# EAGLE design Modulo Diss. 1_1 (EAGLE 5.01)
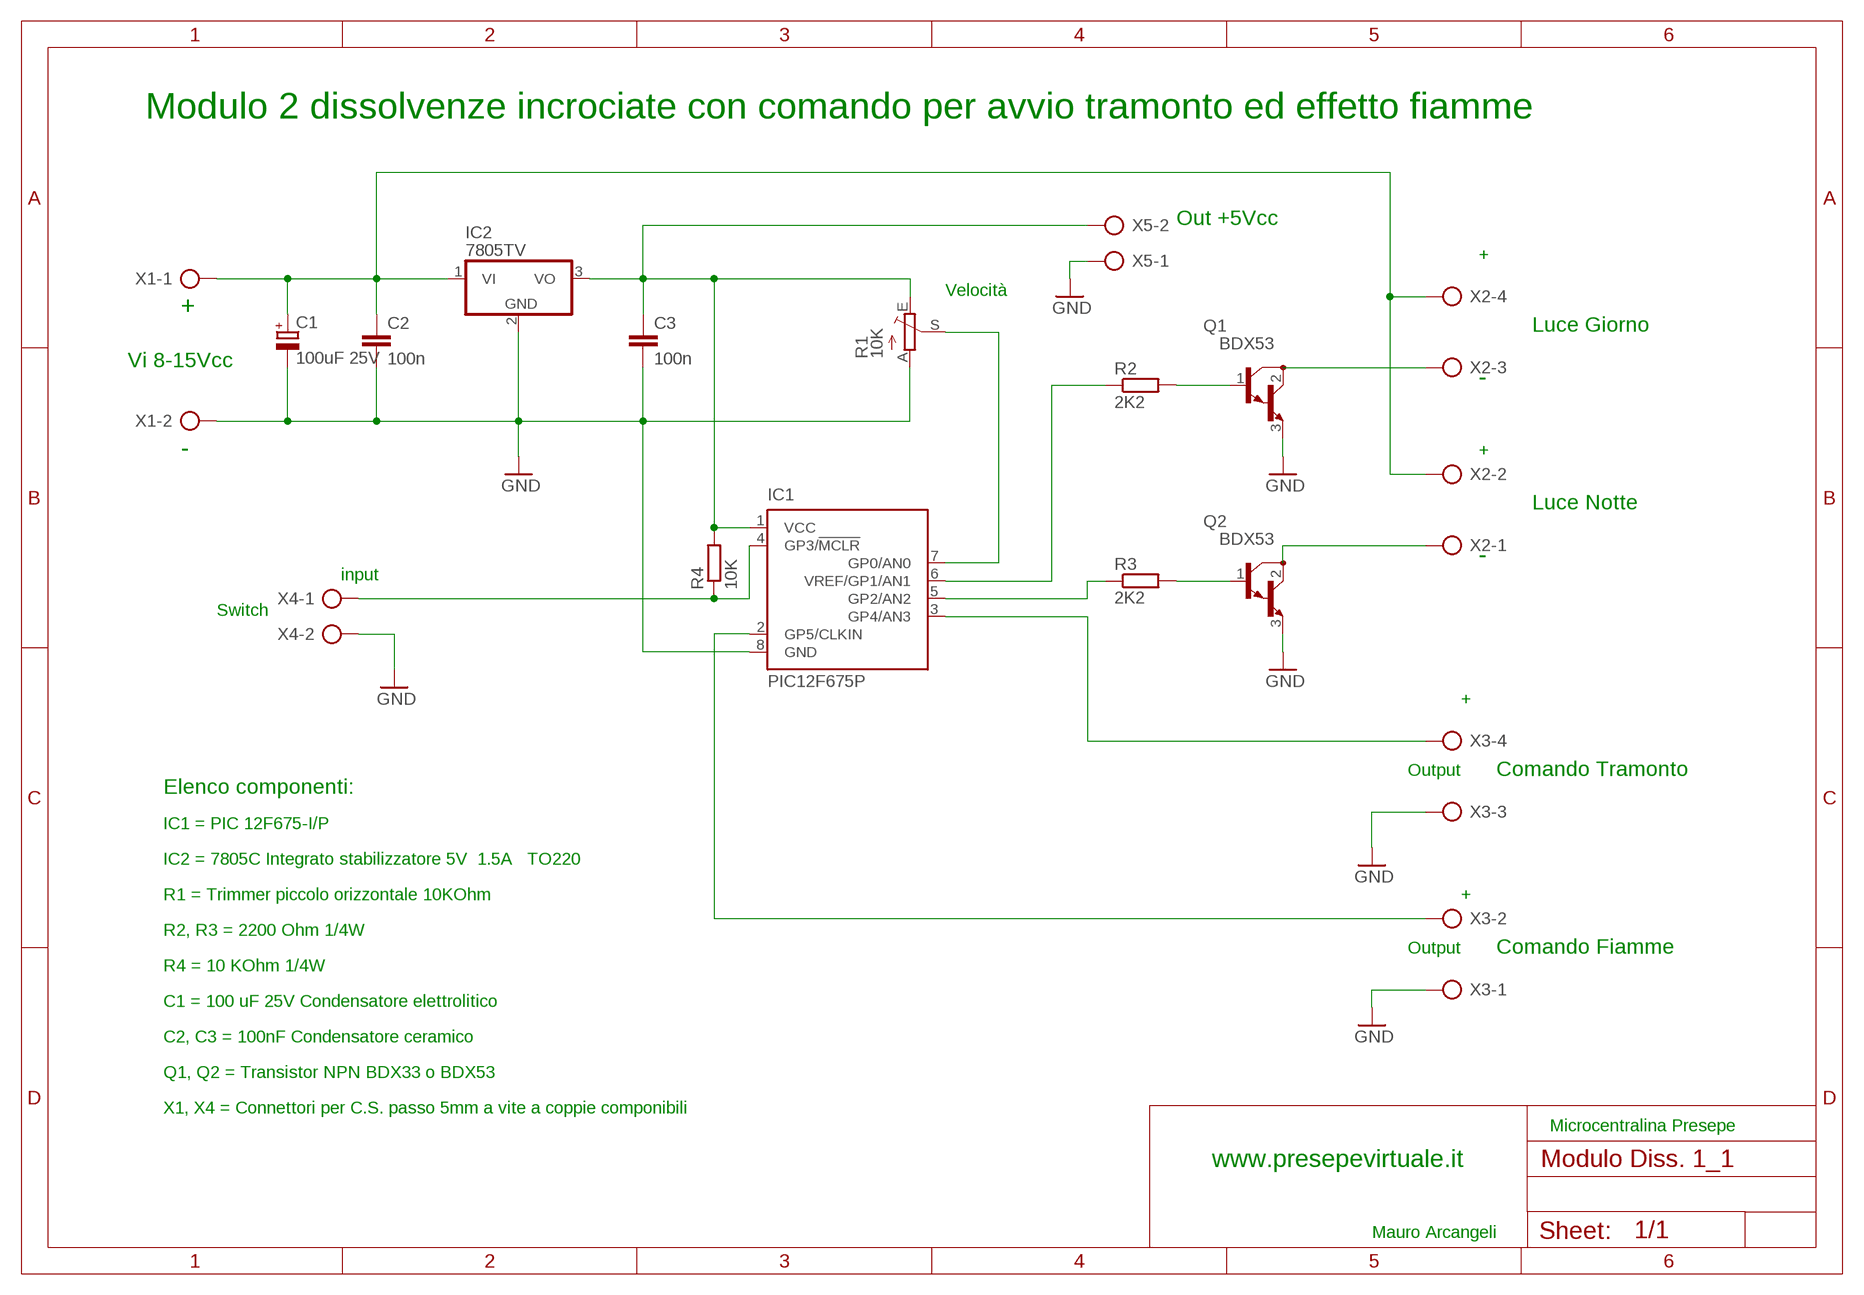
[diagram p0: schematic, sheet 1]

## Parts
C1  100uF 25V  CPOL-EUE3.5-8  [E3,5-8]
C2  100n  C-EU050-025X075  [C050-025X075]
C3  100n  C-EU050-025X075  [C050-025X075]
IC1  PIC12F675P  [DIL8]
IC2  7805TV  [TO220V]
Q1  BDX53  [TO220]
Q2  BDX53  [TO220]
R1  10K  TRIM_EU-PT10  [PT-10]
R2  2K2  R-EU_0207/12  [0207/12]
R3  2K2  R-EU_0207/12  [0207/12]
R4  10K  R-EU_0207/12  [0207/12]
X1  AK500/2  [AK500/2]
X2  AK500/4  [AK500/4]
X3  AK500/4  [AK500/4]
X4  AK500/2  [AK500/2]
X5  AK500/2  [AK500/2]

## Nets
GND: C1.- C2.2 C3.2 IC1.8(GND) IC2.2(GND) Q1.3(E) Q2.3(E) R1.A X1.2 X3.1 X3.3 X4.2 X5.1
N$1: C1.+ C2.1 IC2.1(VI) X1.1 X2.2 X2.4
N$2: C3.1 IC1.1(VCC) IC2.3(VO) R1.E R4.2 X5.2
N$4: Q1.1(B) R2.2
N$5: Q2.1(B) R3.2
N$6: Q2.2(C) X2.1
N$7: Q1.2(C) X2.3
N$8: IC1.7(GP0/AN0) R1.S
N$9: IC1.4(GP3/!MCLR) R4.1 X4.1
N$10: IC1.6(VREF/GP1/AN1) R2.1
N$11: IC1.5(GP2/AN2) R3.1
N$12: IC1.3(GP4/AN3) X3.4
N$13: IC1.2(GP5/CLKIN) X3.2

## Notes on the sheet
- Modulo 2 dissolvenze incrociate con comando per avvio tramonto ed effetto fiamme
- Out +5Vcc
- +
- Velocità
- +
- Luce Giorno
- Vi 8-15Vcc
- -
- - | +
- Luce Notte
- -
- input
- Switch
- +
- Output | Comando Tramonto
- Elenco componenti:
- IC1 = PIC 12F675-I/P
- IC2 = 7805C Integrato stabilizzatore 5V  1.5A   TO220
- R1 = Trimmer piccolo orizzontale 10KOhm | +
- R2, R3 = 2200 Ohm 1/4W
- Output | Comando Fiamme
- R4 = 10 KOhm 1/4W
- C1 = 100 uF 25V Condensatore elettrolitico
- C2, C3 = 100nF Condensatore ceramico
- Q1, Q2 = Transistor NPN BDX33 o BDX53
- X1, X4 = Connettori per C.S. passo 5mm a vite a coppie componibili
- Microcentralina Presepe
- www.presepevirtuale.it
- Mauro Arcangeli

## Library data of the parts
C1 = rcl:CPOL-EU: POLARIZED CAPACITOR, European symbol
C2 C3 = rcl:C-EU: CAPACITOR, European symbol
IC1 = microchip:PIC12F675: 8-Pin FLASH-Based 8-Bit CMOS Microcontroller Precision Internal 4 MHz oscillator factory calibrated to ±1% Low Power Features: Standby Current: - 1 nA @ 2.0V, typical Operating Current: - 8.5&micro;A @ 32 kHz, 2.0V, typical - 100&micro;A @ 1 MHz, 2.0V, typical Watchdog Timer Current: - 300 nA @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
IC2 = linear:78*: Positive VOLTAGE REGULATOR Source: http://cache.national.com/ds/LM/LM78L05.pdf http://www.fairchildsemi.com/ds/LM/LM7805.pdf
Q1 Q2 = transistor-npn:BDX53*: NPN Darlington Transistor
R1 = pot:TRIM_EU-: POTENTIOMETER
R2-R4 = rcl:R-EU_: RESISTOR, European symbol
X1 X4 X5 = con-ptr500:AK500/2: CONNECTOR
X2 X3 = con-ptr500:AK500/4: CONNECTOR

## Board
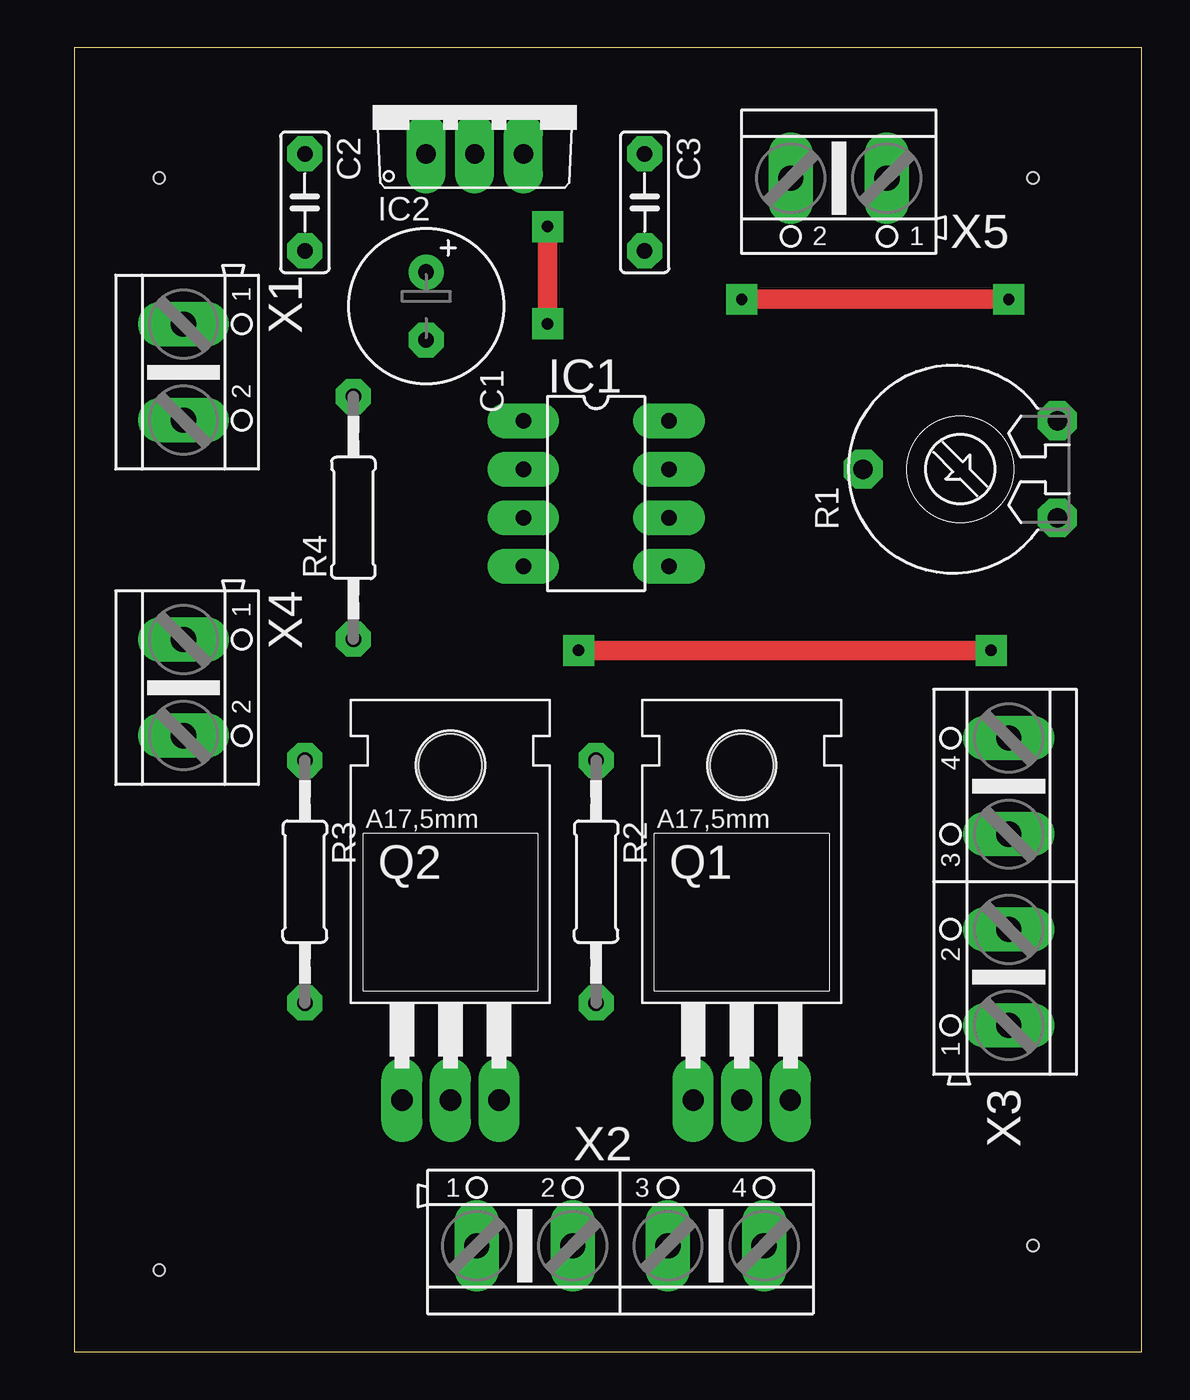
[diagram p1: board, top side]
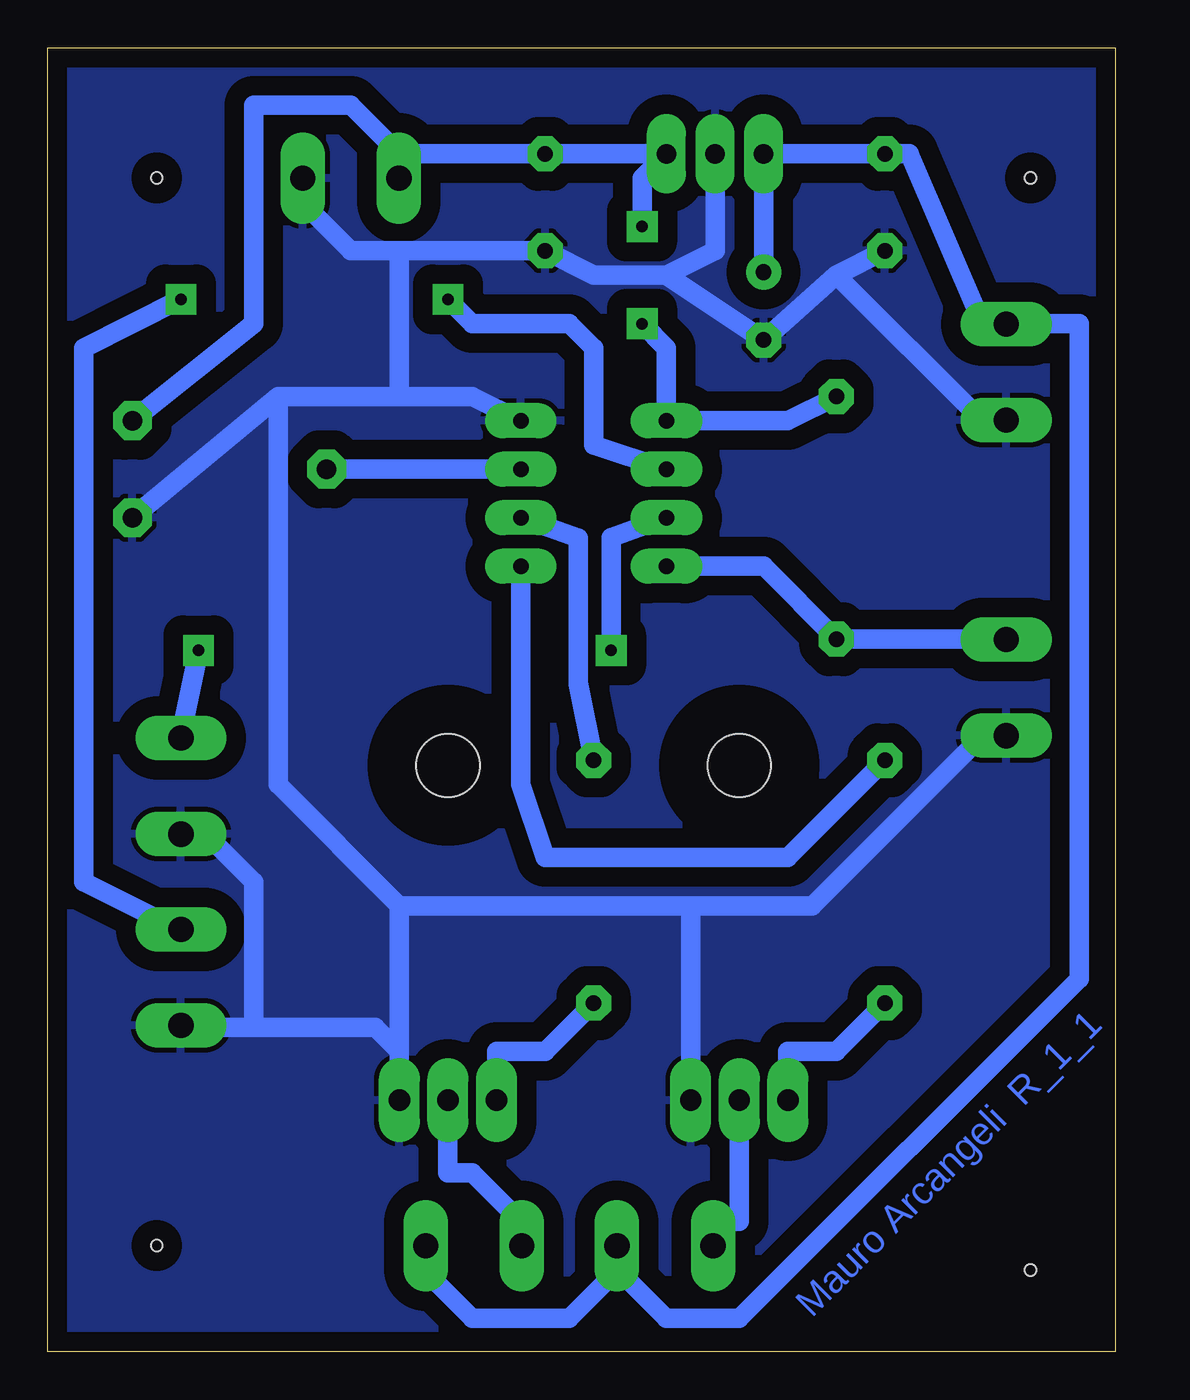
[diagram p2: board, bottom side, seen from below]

Size 55.86 x 68.25 mm. Coordinates in mm from the lower left corner, seen from the top.
Outline: 0,0 55.86,0 55.86,68.25 0,68.25 0,0
Copper layers (1*16): Top 0.035mm / dielectric 1.5mm / Bottom 0.035mm
Design rules "default *": minimum track width 40mil, minimum drill 24mil, track to track 40mil, track to pad 40mil, pad to pad 20mil, via to via 20mil, smd to smd 8mil, copper to edge 40mil, drill to drill 8mil, minimum pad ring 20mil, minimum via ring 20mil, stop-mask expansion 4mil, vias tented up to drill 0mil, thermal gap 10mil
Holes 0.6 mm at 4.44,61.43 50.16,61.43 50.16,5.55 4.44,4.28

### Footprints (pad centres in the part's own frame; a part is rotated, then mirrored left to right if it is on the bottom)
E3,5-8 = drill 0.813 pad 1.6 round: + -1.778,0 | drill 0.813 pad 1.6 octagon: - 1.778,0
C050-025X075 = drill 0.813 octagon: 1 -2.54,0; 2 2.54,0
DIL8 = drill 0.813 long: 1 -3.81,-3.81; 2 -1.27,-3.81; 3 1.27,-3.81; 4 3.81,-3.81; 5 3.81,3.81; 6 1.27,3.81; 7 -1.27,3.81; 8 -3.81,3.81
TO220V = drill 1.016 long: 1 -2.54,-2.54; 2 0,-2.54; 3 2.54,-2.54
TO220 = drill 1.118 long: 1 -2.54,-6.35; 2 0,-6.35; 3 2.54,-6.35 | hole 3.302: 0,11.176
PT-10 = drill 1.016 octagon: A -2.54,-5.08; E 2.54,-5.08; S 0,5.08
0207/12 = drill 0.813 octagon: 1 -6.35,0; 2 6.35,0
AK500/2 = drill 1.321 long: 1 -2.515,0; 2 2.515,0
AK500/4 = drill 1.321 long: 1 -7.518,0; 2 -2.489,0; 3 2.489,0; 4 7.518,0

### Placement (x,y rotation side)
C1  18.41,54.73 270 top
C2  12.06,60.16 270 top
C3  29.84,60.16 270 top
IC1  27.3,44.92 270 top
IC2  20.95,65.24 0 top
Q1  34.92,19.52 0 top
Q2  19.68,19.52 0 top
R1  46.35,46.19 90 top
R2  27.3,24.6 270 top
R3  12.06,24.6 270 top
R4  14.6,43.65 90 top
X1  5.71,51.27 270 top
X2  28.57,5.55 0 top
X3  48.89,24.6 90 top
X4  5.71,34.76 270 top
X5  40,61.43 180 top

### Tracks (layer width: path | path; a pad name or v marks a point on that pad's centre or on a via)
GND
  Bottom 1.016: 37.46,15.71 38.73,16.98 45.08,16.98 | 45.08,16.98 47.62,16.98 X3.1 | 45.08,16.98 45.08,24.6 47.62,27.14 X3.3 | 22.22,23.33 15.87,23.33 6.98,32.22 X4.2 | Q2.3 22.22,23.33 | 37.46,23.33 37.46,15.71 | 22.22,23.33 37.46,23.33 | 37.46,15.71 Q1.3 | 14.6,56.35 C1.- 23.49,56.35 | 14.6,56.35 C2.2 | 14.6,56.35 6.98,48.73 X1.2 | 37.46,50 37.46,57.62 | 37.46,50 33.65,50 IC1.8 | 37.46,57.62 C3.2 27.3,56.35 23.49,56.35 | 43.81,50 R1.A | 43.81,50 37.46,50 | 23.49,56.35 20.95,57.62 IC2.2 | 37.46,57.62 40,57.62 42.54,60.16 X5.1 | 37.46,23.33 43.81,29.68 43.81,50
  pour Bottom: 0.63,67.78 55.24,67.78 55.24,0.47 0.63,0.47
N$1
  Bottom 1.016: 26.03,4.28 28.57,1.74 33.65,1.74 36.19,4.28 X2.4 | C1.+ IC2.1 C2.1 10.79,62.7 6.98,53.81 X1.1 4.44,53.81 1.9,53.81 1.9,19.52 19.68,1.74 23.49,1.74 26.03,4.28 | 26.03,4.28 X2.2
N$2  (via drill 0.6)
  Top 1.016: v24.76,53.81 v24.76,58.89
  Bottom 1.016: 37.46,62.7 C3.1 IC2.3 24.76,61.43 v24.76,58.89 | R4.2 17.14,48.73 IC1.1 23.49,52.54 v24.76,53.81 | R1.E 45.08,53.81 45.08,65.24 40,65.24 37.46,62.7 | 37.46,62.7 X5.2
N$4
  Bottom 1.016: R2.2 29.84,15.71 32.38,15.71 Q1.1
N$5
  Bottom 1.016: R3.2 14.6,15.71 17.14,15.71 Q2.1
N$6
  Bottom 1.016: Q2.2 19.68,6.82 20.95,6.82 X2.1
N$7
  Bottom 1.016: Q1.2 34.92,9.36 33.65,9.36 31.11,6.82 X2.3
N$8
  Bottom 1.016: IC1.7 R1.S
N$9
  Bottom 1.016: IC1.4 18.41,41.11 R4.1 6.98,37.3 X4.1
N$10
  Bottom 1.016: R2.1 28.1,34.97 28.1,42.59 IC1.6
N$11
  Bottom 1.016: R3.1 17.14,25.87 29.84,25.87 31.11,29.68 IC1.5
N$12  (via drill 0.6)
  Top 1.016: v26.38,36.71 v47.97,36.71
  Bottom 1.016: IC1.3 26.38,42.62 v26.38,36.71 | X3.4 48.89,32.22 v47.97,36.71
N$13  (via drill 0.6)
  Top 1.016: v48.89,55.08 v34.92,55.08
  Bottom 1.016: IC1.2 27.3,47.46 27.3,52.54 28.57,53.81 33.65,53.81 v34.92,55.08 | v48.89,55.08 53.97,52.54 53.97,24.6 48.89,22.06 X3.2

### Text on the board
Bottom: Mauro Arcangeli R_1_1
Document: Uscita stabilizzata 5Vcc | + | - | + | Alimentazione 8-12Vcc | - | + | Input (non utilizzato) | + | - | Out Comando Modulo Tramonto | - | + | Out Comando Modulo Fiamme | - | - | + | - | + | Out Notte | Out Giorno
